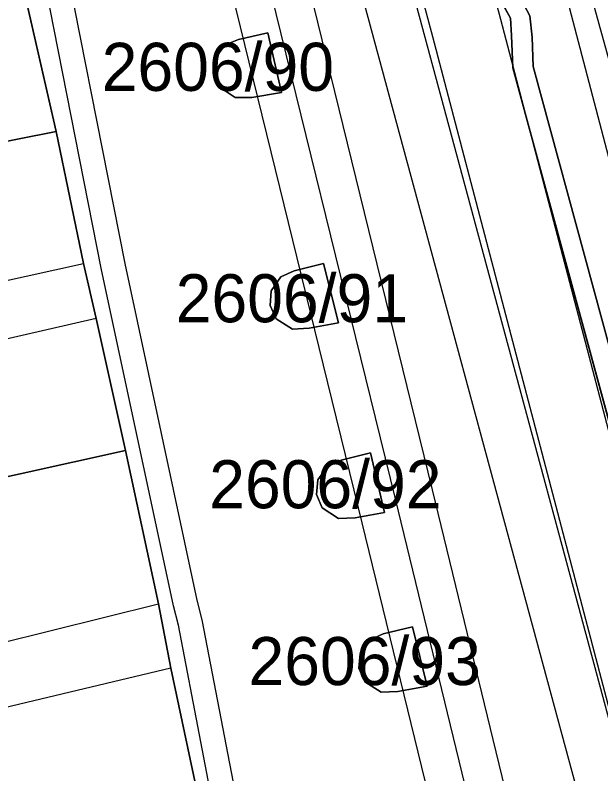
# Model space of a CAD drawing. Extents: x -263423 to -261326, y -1240067 to -1237864.
# Drawn here: x -262914.31 to -262889.94, y -1239229.98 to -1239198.41 of the extents above; entities that cross this region are included whole.
import ezdxf

# ---------------------------------------------------------------- set-up
doc = ezdxf.new("R2010")
doc.units = 0
for name, color, linetype in [('body_kn', 7, 'Continuous'), ('kladpar_druhypozemkov', 7, 'Continuous'), ('kladpar_hranice', 7, 'Continuous'), ('kladpar_parcelnecisla', 7, 'Continuous'), ('kladpar_plochy', 7, 'Continuous'), ('tarchy_linie', 7, 'Continuous'), ('zappar_hrandruhpozemk', 7, 'Continuous')]:
    doc.layers.add(name, color=color, linetype=linetype)

msp = doc.modelspace()

# ---------------------------------------------------------------- linework, layer by layer
at = {"layer": 'body_kn'}
for p, q in [((-262894.12, -1239198.57), (-262894.12, -1239198.57)), ((-262893.7, -1239198.54), (-262893.7, -1239198.54)), ((-262892.9, -1239198.44), (-262892.9, -1239198.44)), ((-262903.79, -1239199.14), (-262903.79, -1239199.14)), ((-262896.93, -1239199.31), (-262896.93, -1239199.31)), ((-262893.66, -1239199.26), (-262893.66, -1239199.26)), ((-262905.01, -1239199.42), (-262905.01, -1239199.42)), ((-262892.79, -1239199.33), (-262892.79, -1239199.33)), ((-262905.57, -1239199.65), (-262905.57, -1239199.65)), ((-262906, -1239200.23), (-262906, -1239200.23)), ((-262892.76, -1239200.55), (-262892.76, -1239200.55)), ((-262906.06, -1239200.83), (-262906.06, -1239200.83)), ((-262893.6, -1239200.6), (-262893.6, -1239200.6)), ((-262905.82, -1239201.39), (-262905.82, -1239201.39)), ((-262904.46, -1239201.83), (-262904.46, -1239201.83)), ((-262903.23, -1239201.63), (-262903.23, -1239201.63)), ((-262903.23, -1239201.63), (-262903.23, -1239201.63)), ((-262905.15, -1239201.84), (-262905.15, -1239201.84)), ((-262912.6, -1239203.25), (-262912.6, -1239203.25)), ((-262911.46, -1239208.74), (-262911.46, -1239208.74)), ((-262909.75, -1239208.74), (-262909.75, -1239208.74)), ((-262901.48, -1239208.74), (-262901.48, -1239208.74)), ((-262910.73, -1239208.94), (-262910.73, -1239208.94)), ((-262902.7, -1239209.05), (-262902.7, -1239209.05)), ((-262903.25, -1239209.3), (-262903.25, -1239209.3)), ((-262903.66, -1239209.88), (-262903.66, -1239209.88)), ((-262903.7, -1239210.49), (-262903.7, -1239210.49)), ((-262910.94, -1239211.03), (-262910.94, -1239211.03)), ((-262910.94, -1239211.03), (-262910.94, -1239211.03)), ((-262903.45, -1239211.05), (-262903.45, -1239211.05)), ((-262900.86, -1239211.21), (-262900.86, -1239211.21)), ((-262900.86, -1239211.21), (-262900.86, -1239211.21)), ((-262902.77, -1239211.48), (-262902.77, -1239211.48)), ((-262902.08, -1239211.44), (-262902.08, -1239211.44)), ((-262909.72, -1239216.53), (-262909.72, -1239216.53)), ((-262899.53, -1239216.63), (-262899.53, -1239216.63)), ((-262900.75, -1239216.93), (-262900.75, -1239216.93)), ((-262901.3, -1239217.17), (-262901.3, -1239217.17)), ((-262901.72, -1239217.75), (-262901.72, -1239217.75)), ((-262896.96, -1239218.17), (-262896.96, -1239218.17)), ((-262901.77, -1239218.36), (-262901.77, -1239218.36)), ((-262898.49, -1239218.54), (-262898.49, -1239218.54)), ((-262901.53, -1239218.91), (-262901.53, -1239218.91)), ((-262900.02, -1239218.91), (-262900.02, -1239218.91)), ((-262898.94, -1239219.11), (-262898.94, -1239219.11)), ((-262898.94, -1239219.11), (-262898.94, -1239219.11)), ((-262900.85, -1239219.35), (-262900.85, -1239219.35)), ((-262900.16, -1239219.33), (-262900.16, -1239219.33)), ((-262908.34, -1239222.91), (-262908.34, -1239222.91)), ((-262906.75, -1239222.76), (-262906.75, -1239222.76)), ((-262907.72, -1239222.99), (-262907.72, -1239222.99)), ((-262906.54, -1239223.58), (-262906.54, -1239223.58)), ((-262907.52, -1239223.8), (-262907.52, -1239223.8)), ((-262897.77, -1239223.86), (-262897.77, -1239223.86)), ((-262898.99, -1239224.16), (-262898.99, -1239224.16)), ((-262899.54, -1239224.4), (-262899.54, -1239224.4)), ((-262899.96, -1239224.99), (-262899.96, -1239224.99)), ((-262907.83, -1239225.59), (-262907.83, -1239225.59)), ((-262907.83, -1239225.59), (-262907.83, -1239225.59)), ((-262900.01, -1239225.59), (-262900.01, -1239225.59)), ((-262899.76, -1239226.15), (-262899.76, -1239226.15)), ((-262897.17, -1239226.34), (-262897.17, -1239226.34)), ((-262897.17, -1239226.34), (-262897.17, -1239226.34)), ((-262899.08, -1239226.59), (-262899.08, -1239226.59)), ((-262898.39, -1239226.56), (-262898.39, -1239226.56))]:
    msp.add_line(p, q, dxfattribs=at)
at = {"layer": 'kladpar_druhypozemkov'}
for p, q in [((-262904.68, -1239200.35), (-262904.68, -1239200.35)), ((-262902.52, -1239210.09), (-262902.52, -1239210.09)), ((-262900.65, -1239217.8), (-262900.65, -1239217.8)), ((-262898.63, -1239225.29), (-262898.63, -1239225.29))]:
    msp.add_line(p, q, dxfattribs=at)
at = {"layer": 'kladpar_hranice'}
for points in [[(-262915.79, -1239189.13), (-262914.57, -1239194.5), (-262914.05, -1239196.92), (-262912.6, -1239203.25), (-262935.42, -1239207.77), (-262936.75, -1239201.89), (-262937.57, -1239198.76), (-262960.08, -1239203.61), (-262961.06, -1239204.86), (-262965.97, -1239206.09), (-262965.62, -1239207.43), (-262963.93, -1239214.46), (-262974.91, -1239217.46), (-262976.66, -1239210.24), (-262977.01, -1239208.77), (-262978.29, -1239203.66), (-262963.77, -1239198.38), (-262944.57, -1239194.04), (-262915.79, -1239189.13)], [(-262900.99, -1239258.02), (-262904.73, -1239240.4), (-262905.24, -1239237.91), (-262905.71, -1239235.87), (-262906.56, -1239231.59), (-262907.83, -1239225.59), (-262908.34, -1239222.91), (-262909.72, -1239216.53), (-262910.94, -1239211.03), (-262911.46, -1239208.74), (-262912.6, -1239203.25), (-262914.05, -1239196.92)], [(-262893.54, -1239197.19), (-262892.9, -1239198.44), (-262892.79, -1239199.33), (-262892.76, -1239200.55), (-262875.18, -1239265.22), (-262874.5, -1239267.72), (-262870.89, -1239281.4), (-262870.34, -1239282.54), (-262869.36, -1239283.93), (-262868.26, -1239285.19), (-262869.45, -1239288.25), (-262872.13, -1239286.35), (-262871.76, -1239284.74), (-262871.59, -1239282.87), (-262871.66, -1239281.54), (-262875.31, -1239267.94), (-262876, -1239265.39), (-262893.6, -1239200.6), (-262893.66, -1239199.26), (-262893.7, -1239198.54), (-262894.26, -1239197.51)], [(-262894.26, -1239197.51), (-262893.7, -1239198.54), (-262893.66, -1239199.26), (-262893.6, -1239200.6), (-262876, -1239265.39), (-262875.31, -1239267.94), (-262871.66, -1239281.54), (-262871.59, -1239282.87), (-262871.76, -1239284.74), (-262872.13, -1239286.35), (-262869.45, -1239288.25), (-262868.26, -1239285.19), (-262869.36, -1239283.93), (-262870.34, -1239282.54), (-262870.89, -1239281.4), (-262874.5, -1239267.72), (-262875.18, -1239265.22), (-262892.76, -1239200.55), (-262892.79, -1239199.33), (-262892.9, -1239198.44), (-262893.54, -1239197.19)], [(-262903.23, -1239201.63), (-262904.46, -1239201.83), (-262905.15, -1239201.84), (-262905.82, -1239201.39), (-262906.06, -1239200.83), (-262906, -1239200.23), (-262905.57, -1239199.65), (-262905.01, -1239199.42), (-262903.79, -1239199.14), (-262903.23, -1239201.63)], [(-262904.46, -1239201.83), (-262903.23, -1239201.63), (-262903.79, -1239199.14), (-262905.01, -1239199.42), (-262905.57, -1239199.65), (-262906, -1239200.23), (-262906.06, -1239200.83), (-262905.82, -1239201.39), (-262905.15, -1239201.84), (-262904.46, -1239201.83)], [(-262939.31, -1239208.7), (-262935.42, -1239207.77), (-262912.6, -1239203.25), (-262911.46, -1239208.74), (-262910.94, -1239211.03), (-262909.72, -1239216.53), (-262938.48, -1239222.89), (-262941.03, -1239223.47), (-262952.38, -1239226.02), (-262959.28, -1239227.78)], [(-262900.86, -1239211.21), (-262902.08, -1239211.44), (-262902.77, -1239211.48), (-262903.45, -1239211.05), (-262903.7, -1239210.49), (-262903.66, -1239209.88), (-262903.25, -1239209.3), (-262902.7, -1239209.05), (-262901.48, -1239208.74), (-262900.86, -1239211.21)], [(-262902.08, -1239211.44), (-262900.86, -1239211.21), (-262901.48, -1239208.74), (-262902.7, -1239209.05), (-262903.25, -1239209.3), (-262903.66, -1239209.88), (-262903.7, -1239210.49), (-262903.45, -1239211.05), (-262902.77, -1239211.48), (-262902.08, -1239211.44)], [(-262952.38, -1239226.02), (-262941.03, -1239223.47), (-262938.48, -1239222.89), (-262909.72, -1239216.53), (-262908.34, -1239222.91), (-262907.83, -1239225.59), (-262906.56, -1239231.59), (-262945.04, -1239241.24), (-262955.94, -1239243.48), (-262964.73, -1239245.13), (-262964.91, -1239244.43), (-262966.03, -1239240.53), (-262966.32, -1239239.25), (-262966.96, -1239236.76), (-262968.72, -1239230.3), (-262964.06, -1239229.07), (-262959.28, -1239227.78), (-262952.38, -1239226.02)], [(-262898.94, -1239219.11), (-262900.16, -1239219.33), (-262900.85, -1239219.35), (-262901.53, -1239218.91), (-262901.77, -1239218.36), (-262901.72, -1239217.75), (-262901.3, -1239217.17), (-262900.75, -1239216.93), (-262899.53, -1239216.63), (-262898.94, -1239219.11)], [(-262900.16, -1239219.33), (-262898.94, -1239219.11), (-262899.53, -1239216.63), (-262900.75, -1239216.93), (-262901.3, -1239217.17), (-262901.72, -1239217.75), (-262901.77, -1239218.36), (-262901.53, -1239218.91), (-262900.85, -1239219.35), (-262900.16, -1239219.33)], [(-262897.17, -1239226.34), (-262898.39, -1239226.56), (-262899.08, -1239226.59), (-262899.76, -1239226.15), (-262900.01, -1239225.59), (-262899.96, -1239224.99), (-262899.54, -1239224.4), (-262898.99, -1239224.16), (-262897.77, -1239223.86), (-262897.17, -1239226.34)], [(-262898.39, -1239226.56), (-262897.17, -1239226.34), (-262897.77, -1239223.86), (-262898.99, -1239224.16), (-262899.54, -1239224.4), (-262899.96, -1239224.99), (-262900.01, -1239225.59), (-262899.76, -1239226.15), (-262899.08, -1239226.59), (-262898.39, -1239226.56)]]:
    msp.add_lwpolyline(points, dxfattribs=at)
at = {"layer": 'kladpar_plochy'}
for p, q in [((-262912.6, -1239203.25), (-262914.05, -1239196.92)), ((-262892.9, -1239198.44), (-262893.54, -1239197.19)), ((-262894.26, -1239197.51), (-262893.7, -1239198.54)), ((-262893.7, -1239198.54), (-262893.66, -1239199.26)), ((-262892.79, -1239199.33), (-262892.9, -1239198.44)), ((-262903.79, -1239199.14), (-262905.01, -1239199.42)), ((-262903.23, -1239201.63), (-262903.79, -1239199.14)), ((-262893.66, -1239199.26), (-262893.6, -1239200.6)), ((-262905.01, -1239199.42), (-262905.57, -1239199.65)), ((-262892.76, -1239200.55), (-262892.79, -1239199.33)), ((-262905.57, -1239199.65), (-262906, -1239200.23)), ((-262906, -1239200.23), (-262906.06, -1239200.83)), ((-262875.18, -1239265.22), (-262892.76, -1239200.55)), ((-262906.06, -1239200.83), (-262905.82, -1239201.39)), ((-262893.6, -1239200.6), (-262876, -1239265.39)), ((-262905.82, -1239201.39), (-262905.15, -1239201.84)), ((-262905.15, -1239201.84), (-262904.46, -1239201.83)), ((-262904.46, -1239201.83), (-262903.23, -1239201.63)), ((-262911.46, -1239208.74), (-262912.6, -1239203.25)), ((-262910.94, -1239211.03), (-262911.46, -1239208.74)), ((-262901.48, -1239208.74), (-262902.7, -1239209.05)), ((-262900.86, -1239211.21), (-262901.48, -1239208.74)), ((-262902.7, -1239209.05), (-262903.25, -1239209.3)), ((-262903.25, -1239209.3), (-262903.66, -1239209.88)), ((-262903.66, -1239209.88), (-262903.7, -1239210.49)), ((-262903.7, -1239210.49), (-262903.45, -1239211.05)), ((-262909.72, -1239216.53), (-262910.94, -1239211.03)), ((-262903.45, -1239211.05), (-262902.77, -1239211.48)), ((-262902.08, -1239211.44), (-262900.86, -1239211.21)), ((-262902.77, -1239211.48), (-262902.08, -1239211.44)), ((-262908.34, -1239222.91), (-262909.72, -1239216.53)), ((-262899.53, -1239216.63), (-262900.75, -1239216.93)), ((-262898.94, -1239219.11), (-262899.53, -1239216.63)), ((-262900.75, -1239216.93), (-262901.3, -1239217.17)), ((-262901.3, -1239217.17), (-262901.72, -1239217.75)), ((-262901.72, -1239217.75), (-262901.77, -1239218.36)), ((-262901.77, -1239218.36), (-262901.53, -1239218.91)), ((-262901.53, -1239218.91), (-262900.85, -1239219.35)), ((-262900.16, -1239219.33), (-262898.94, -1239219.11)), ((-262900.85, -1239219.35), (-262900.16, -1239219.33)), ((-262907.83, -1239225.59), (-262908.34, -1239222.91)), ((-262897.77, -1239223.86), (-262898.99, -1239224.16)), ((-262897.17, -1239226.34), (-262897.77, -1239223.86)), ((-262898.99, -1239224.16), (-262899.54, -1239224.4)), ((-262899.54, -1239224.4), (-262899.96, -1239224.99)), ((-262899.96, -1239224.99), (-262900.01, -1239225.59)), ((-262906.56, -1239231.59), (-262907.83, -1239225.59)), ((-262900.01, -1239225.59), (-262899.76, -1239226.15)), ((-262899.76, -1239226.15), (-262899.08, -1239226.59)), ((-262898.39, -1239226.56), (-262897.17, -1239226.34)), ((-262899.08, -1239226.59), (-262898.39, -1239226.56))]:
    msp.add_line(p, q, dxfattribs=at)
for points in [[(-262915.79, -1239189.13), (-262914.57, -1239194.5), (-262914.05, -1239196.92), (-262912.6, -1239203.25), (-262935.42, -1239207.77), (-262936.75, -1239201.89), (-262937.57, -1239198.76), (-262960.08, -1239203.61), (-262961.06, -1239204.86), (-262965.97, -1239206.09), (-262965.62, -1239207.43), (-262963.93, -1239214.46), (-262974.91, -1239217.46), (-262976.66, -1239210.24), (-262977.01, -1239208.77), (-262978.29, -1239203.66), (-262963.77, -1239198.38), (-262944.57, -1239194.04)], [(-262903.23, -1239201.63), (-262904.46, -1239201.83), (-262905.15, -1239201.84), (-262905.82, -1239201.39), (-262906.06, -1239200.83), (-262906, -1239200.23), (-262905.57, -1239199.65), (-262905.01, -1239199.42), (-262903.79, -1239199.14)], [(-262939.31, -1239208.7), (-262935.42, -1239207.77), (-262912.6, -1239203.25), (-262911.46, -1239208.74), (-262910.94, -1239211.03), (-262909.72, -1239216.53), (-262938.48, -1239222.89), (-262941.03, -1239223.47), (-262952.38, -1239226.02), (-262959.28, -1239227.78), (-262964.06, -1239229.07), (-262968.72, -1239230.3), (-262972.87, -1239231.29), (-262980.72, -1239233.28), (-262983.46, -1239233.98), (-262991.75, -1239236.03), (-262998.77, -1239237.78), (-263000.37, -1239229.36), (-263001.4, -1239224.25), (-263001.08, -1239224.13), (-262983.85, -1239219.81), (-262974.91, -1239217.46), (-262963.93, -1239214.46), (-262958.89, -1239213.23)], [(-262900.86, -1239211.21), (-262902.08, -1239211.44), (-262902.77, -1239211.48), (-262903.45, -1239211.05), (-262903.7, -1239210.49), (-262903.66, -1239209.88), (-262903.25, -1239209.3), (-262902.7, -1239209.05), (-262901.48, -1239208.74)], [(-262952.38, -1239226.02), (-262941.03, -1239223.47), (-262938.48, -1239222.89), (-262909.72, -1239216.53), (-262908.34, -1239222.91), (-262907.83, -1239225.59), (-262906.56, -1239231.59), (-262945.04, -1239241.24), (-262955.94, -1239243.48), (-262964.73, -1239245.13), (-262964.91, -1239244.43), (-262966.03, -1239240.53), (-262966.32, -1239239.25), (-262966.96, -1239236.76), (-262968.72, -1239230.3), (-262964.06, -1239229.07), (-262959.28, -1239227.78)], [(-262898.94, -1239219.11), (-262900.16, -1239219.33), (-262900.85, -1239219.35), (-262901.53, -1239218.91), (-262901.77, -1239218.36), (-262901.72, -1239217.75), (-262901.3, -1239217.17), (-262900.75, -1239216.93), (-262899.53, -1239216.63)], [(-262897.17, -1239226.34), (-262898.39, -1239226.56), (-262899.08, -1239226.59), (-262899.76, -1239226.15), (-262900.01, -1239225.59), (-262899.96, -1239224.99), (-262899.54, -1239224.4), (-262898.99, -1239224.16), (-262897.77, -1239223.86)]]:
    msp.add_lwpolyline(points, close=True, dxfattribs=at)
msp.add_lwpolyline([(-262893.54, -1239197.19), (-262892.9, -1239198.44), (-262892.79, -1239199.33), (-262892.76, -1239200.55), (-262875.18, -1239265.22), (-262874.5, -1239267.72), (-262870.89, -1239281.4), (-262870.34, -1239282.54), (-262869.36, -1239283.93), (-262868.26, -1239285.19), (-262869.45, -1239288.25), (-262872.13, -1239286.35), (-262871.76, -1239284.74), (-262871.59, -1239282.87), (-262871.66, -1239281.54), (-262875.31, -1239267.94), (-262876, -1239265.39), (-262893.6, -1239200.6), (-262893.66, -1239199.26), (-262893.7, -1239198.54), (-262894.26, -1239197.51)], dxfattribs=at)
at = {"layer": 'tarchy_linie'}
for points in [[(-263002.97, -1238844.59), (-262980.25, -1238906.63), (-262945.58, -1239009.09), (-262938.29, -1239035.86), (-262916.38, -1239115.82), (-262894.12, -1239198.57), (-262876.1, -1239267.26), (-262891.06, -1239270.91), (-262884.2, -1239310.37), (-262877, -1239350.49), (-262869.73, -1239390.34), (-262861.27, -1239427.46), (-262857.92, -1239442.13), (-262856.51, -1239448.31), (-262843.28, -1239506.14), (-262818.17, -1239595.69)], [(-262939.39, -1239021.15), (-262934.2, -1239037.72), (-262927.16, -1239063.69), (-262920.98, -1239083.65), (-262911.91, -1239113.75), (-262904.59, -1239137.31), (-262894.43, -1239170.66), (-262879.54, -1239218.96), (-262874.31, -1239236.62), (-262867.48, -1239260.06), (-262865.11, -1239267.42), (-262873.73, -1239264.88), (-262891.31, -1239197.83), (-262913.63, -1239115.08), (-262935.59, -1239035.12), (-262939.39, -1239021.15)], [(-262931.57, -1239078.69), (-262927.11, -1239096.92), (-262921.96, -1239117.89), (-262918.29, -1239132.37), (-262910.23, -1239164.23), (-262903.15, -1239192.92), (-262896.96, -1239218.17), (-262893.46, -1239232.55), (-262888.28, -1239253.85), (-262887.41, -1239260.33), (-262887.33, -1239268.2), (-262879.36, -1239266.25), (-262896.93, -1239199.31), (-262919.13, -1239116.56), (-262940.99, -1239036.6)], [(-262868.1, -1239408.65), (-262872.01, -1239389.76), (-262878.89, -1239354.27), (-262886.38, -1239314.4), (-262887.47, -1239307.93), (-262888.71, -1239296.45), (-262889.24, -1239277.55), (-262888.89, -1239269.8), (-262888.98, -1239260.44), (-262889.83, -1239254.14), (-262894.99, -1239232.92), (-262898.49, -1239218.54), (-262904.68, -1239193.3), (-262911.76, -1239164.61), (-262919.82, -1239132.76), (-262923.49, -1239118.27), (-262928.64, -1239097.29), (-262933.1, -1239079.06)], [(-262869.63, -1239409.04), (-262873.55, -1239390.07), (-262880.44, -1239354.57), (-262887.93, -1239314.68), (-262889.03, -1239308.15), (-262890.28, -1239296.56), (-262890.67, -1239282.8), (-262892.97, -1239269.57), (-262890.47, -1239268.97), (-262890.55, -1239260.55), (-262891.38, -1239254.43), (-262896.52, -1239233.29), (-262900.02, -1239218.91), (-262906.21, -1239193.68), (-262913.29, -1239164.99), (-262921.35, -1239133.15), (-262925.02, -1239118.65), (-262930.17, -1239097.66), (-262934.63, -1239079.43)], [(-262912, -1239272.44), (-262911.43, -1239272.98), (-262900.66, -1239270.87), (-262899.91, -1239271.44), (-262899.03, -1239271.13), (-262897.81, -1239270.71), (-262890.51, -1239271.78), (-262886.1, -1239271.71), (-262884.32, -1239271.83), (-262883.34, -1239272.14), (-262886.65, -1239253.45), (-262895.77, -1239255.25), (-262901, -1239256.19), (-262902.95, -1239245.25), (-262905.65, -1239233.51), (-262907.52, -1239223.8), (-262907.72, -1239222.99), (-262910.73, -1239208.94), (-262913.76, -1239193.57)], [(-262912.78, -1239193.36), (-262909.75, -1239208.74), (-262906.75, -1239222.76), (-262906.54, -1239223.58), (-262904.67, -1239233.3), (-262901.97, -1239245.05), (-262900.19, -1239255.03), (-262895.95, -1239254.27), (-262892.63, -1239253.61), (-262892.57, -1239253.65), (-262891.88, -1239253.63), (-262890.66, -1239253.41), (-262890.7, -1239253.23), (-262886.94, -1239252.51)], [(-262887.46, -1239254.63), (-262895.58, -1239256.23), (-262901.16, -1239257.23), (-262904.73, -1239240.4), (-262905.24, -1239237.91), (-262905.71, -1239235.87), (-262906.56, -1239231.59), (-262907.83, -1239225.59), (-262908.34, -1239222.91), (-262909.72, -1239216.53), (-262910.94, -1239211.03), (-262911.46, -1239208.74), (-262912.6, -1239203.25), (-262914.05, -1239196.92)]]:
    msp.add_lwpolyline(points, dxfattribs=at)
at = {"layer": 'zappar_hrandruhpozemk'}
for p, q in [((-262940.47, -1239215.16), (-262911.46, -1239208.74)), ((-262910.94, -1239211.03), (-262939.89, -1239217.71)), ((-262934.5, -1239229.39), (-262908.34, -1239222.91)), ((-262907.83, -1239225.59), (-262934.11, -1239231.82))]:
    msp.add_line(p, q, dxfattribs=at)
for points in [[(-262893.25, -1239186.79), (-262890.34, -1239197.61), (-262882.69, -1239225.25), (-262880.02, -1239234.88)], [(-262899.73, -1239190.15), (-262889.66, -1239227.51), (-262887.35, -1239236.1)], [(-262901.75, -1239190.68), (-262889.64, -1239235.47), (-262889.43, -1239236.99), (-262889.65, -1239240.01)]]:
    msp.add_lwpolyline(points, dxfattribs=at)

# ---------------------------------------------------------------- texts
at = {"layer": 'kladpar_parcelnecisla'}
for s, p in [('2606/90', (-262910.71, -1239201.56)), ('2606/91', (-262907.63, -1239211.19)), ('2606/92', (-262906.236, -1239218.93)), ('2606/93', (-262904.601, -1239226.29))]:
    msp.add_text(s, height=2, dxfattribs=at).set_placement(p)

doc.saveas('drawing.dxf')
